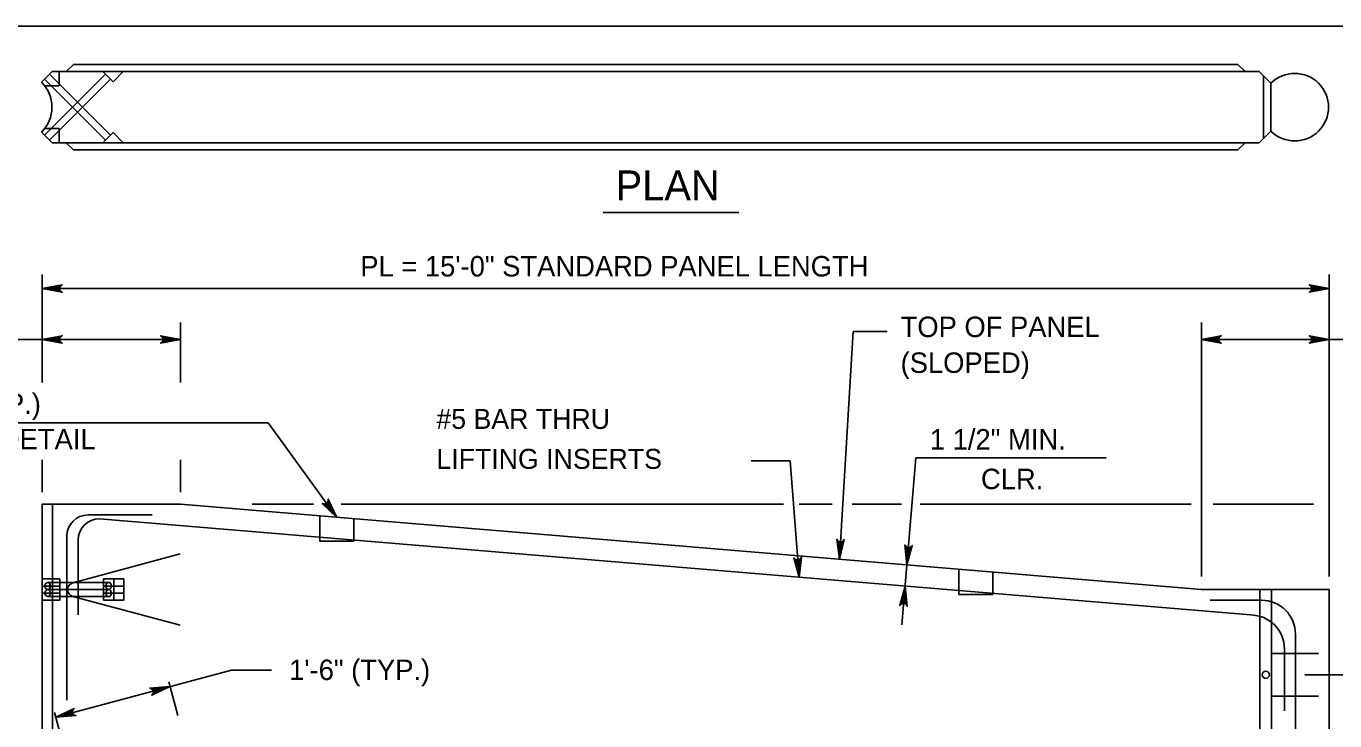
# Model space of a CAD drawing. Extents: x 3385 to 6532, y -616 to 1166.
# Drawn here: x 5133.1 to 5329.7, y 452.4 to 556.7 of the extents above; entities that cross this region are included whole.
import ezdxf

# ---------------------------------------------------------------- set-up
doc = ezdxf.new("R2010")
doc.units = 0
doc.layers.add('1', color=7, linetype='Continuous')
doc.layers.add('2', color=7, linetype='Continuous')

msp = doc.modelspace()

# ---------------------------------------------------------------- linework, layer by layer
at = {"layer": '1'}
for p, q in [((5139.1, 549.87), (5140.17, 550.93)), ((5315.1, 550.93), (5140.17, 550.93)), ((5316.16, 549.87), (5315.1, 550.93)), ((5135.4, 548.3), (5136.97, 549.87)), ((5135.82, 540.35), (5144.98, 549.51)), ((5135.82, 548.72), (5144.98, 539.56)), ((5136.61, 549.51), (5145.77, 540.35)), ((5136.61, 539.56), (5145.77, 548.72)), ((5318.3, 549.87), (5136.97, 549.87)), ((5138.02, 549.87), (5138.02, 547.73)), ((5146.13, 548.36), (5144.62, 549.87)), ((5146.13, 548.36), (5147.63, 549.87)), ((5318.3, 549.87), (5320.05, 548.12)), ((5318.93, 549.23), (5318.93, 539.84)), ((5138.02, 547.73), (5135.88, 547.73)), ((5320.05, 548.11), (5320.05, 540.96)), ((5135.4, 540.77), (5136.97, 539.2)), ((5138.02, 541.33), (5135.88, 541.33)), ((5138.02, 541.33), (5138.02, 539.2)), ((5146.13, 540.71), (5144.62, 539.2)), ((5146.13, 540.71), (5147.63, 539.2)), ((5318.3, 539.2), (5320.05, 540.95)), ((5318.3, 539.2), (5136.97, 539.2)), ((5139.1, 539.2), (5140.17, 538.13)), ((5316.16, 539.2), (5315.1, 538.13)), ((5315.1, 538.13), (5140.17, 538.13)), ((5219.73, 528.7), (5240.11, 528.7)), ((5135.5, 519.39), (5135.5, 503.18)), ((5328.8, 519.39), (5328.8, 474.08)), ((5135.5, 517.29), (5328.8, 517.29)), ((5156.26, 512.21), (5156.26, 503.18)), ((5309.6, 512.21), (5309.6, 474.08)), ((5128.51, 509.66), (5156.26, 509.66)), ((5257.28, 510.87), (5255.23, 476.64)), ((5257.28, 510.87), (5262.42, 510.87)), ((5309.6, 509.66), (5335.1, 509.66)), ((5061.13, 497.15), (5169.45, 497.15)), ((5169.45, 497.15), (5179.75, 482.94)), ((5135.5, 491.58), (5135.5, 486.73)), ((5156.26, 491.58), (5156.26, 486.73)), ((5264.63, 466.82), (5266.72, 491.87)), ((5266.72, 491.87), (5295.32, 491.87)), ((5241.99, 491.42), (5247.85, 491.42)), ((5247.85, 491.42), (5249.19, 473.95)), ((5135.5, 484.9), (5135.5, 329.7)), ((5135.5, 484.9), (5156.26, 484.9)), ((5137.06, 484.9), (5137.06, 329.7)), ((5156.26, 484.9), (5309.6, 472.1)), ((5167.05, 484.9), (5176.22, 484.9)), ((5180.42, 484.9), (5246.84, 484.9)), ((5249.18, 484.9), (5254.13, 484.9)), ((5257.17, 484.9), (5264.57, 484.9)), ((5267.36, 484.9), (5308.06, 484.9)), ((5311.38, 484.9), (5326.45, 484.9)), ((5142.4, 483.3), (5152, 483.3)), ((5144.08, 482.72), (5316.97, 468.29)), ((5177.18, 483.16), (5177.18, 479.36)), ((5182.3, 482.73), (5182.3, 479.36)), ((5139.2, 480.1), (5139.2, 455.47)), ((5140.88, 479.51), (5140.88, 468.32)), ((5177.18, 479.36), (5182.3, 479.36)), ((5156.21, 477.44), (5140.09, 473.12)), ((5273.18, 475.14), (5273.18, 471.35)), ((5278.3, 474.72), (5278.3, 471.35)), ((5145.48, 473.17), (5136.32, 473.17)), ((5145.48, 472.1), (5136.32, 472.1)), ((5146.23, 471.57), (5146.23, 473.7)), ((5309.6, 472.1), (5328.8, 472.1)), ((5318.4, 472.1), (5318.4, 331.3)), ((5320.15, 472.1), (5320.15, 331.3)), ((5328.8, 472.1), (5328.8, 329.7)), ((5145.48, 471.04), (5136.32, 471.04)), ((5140.09, 471.06), (5156.21, 466.74)), ((5146.23, 471.57), (5146.23, 470.5)), ((5273.18, 471.35), (5278.3, 471.35)), ((5310.94, 470.5), (5318.62, 470.5)), ((5323.74, 465.38), (5323.74, 336.42)), ((5320.29, 462.5), (5327.2, 462.5)), ((5322.09, 463.16), (5322.09, 453.89)), ((5137.54, 452.93), (5163.92, 460)), ((5163.92, 460), (5169.91, 460)), ((5155.85, 453.18), (5154.49, 458.23)), ((5325.16, 459.3), (5385.56, 459.3)), ((5320.29, 456.1), (5327.2, 456.1)), ((5138.61, 448.92), (5137.35, 453.64))]:
    msp.add_line(p, q, dxfattribs=at)
for points in [[(5135.5, 517.29), (5138.49, 517.85), (5138.37, 517.77), (5138.26, 517.69), (5138.2, 517.59), (5138.14, 517.49), (5138.12, 517.39), (5138.1, 517.29), (5138.12, 517.19), (5138.14, 517.09), (5138.2, 516.99), (5138.26, 516.89), (5138.37, 516.81), (5138.49, 516.73), (5135.5, 517.29), (5138.37, 516.81), (5138.26, 516.89), (5135.5, 517.29), (5138.2, 516.99), (5138.14, 517.09), (5135.5, 517.29), (5138.12, 517.19), (5138.1, 517.29), (5135.5, 517.29), (5138.12, 517.39), (5138.14, 517.49), (5135.5, 517.29), (5138.2, 517.59), (5138.26, 517.69), (5135.5, 517.29), (5138.37, 517.77)], [(5328.8, 517.29), (5325.82, 516.73), (5325.93, 516.81), (5326.05, 516.89), (5326.11, 516.99), (5326.17, 517.09), (5326.18, 517.19), (5326.2, 517.29), (5326.18, 517.39), (5326.17, 517.49), (5326.11, 517.59), (5326.05, 517.69), (5325.93, 517.77), (5325.82, 517.85), (5328.8, 517.29), (5325.93, 517.77), (5326.05, 517.69), (5328.8, 517.29), (5326.11, 517.59), (5326.17, 517.49), (5328.8, 517.29), (5326.18, 517.39), (5326.2, 517.29), (5328.8, 517.29), (5326.18, 517.19), (5326.17, 517.09), (5328.8, 517.29), (5326.11, 516.99), (5326.05, 516.89), (5328.8, 517.29), (5325.93, 516.81)], [(5135.5, 509.66), (5138.49, 510.22), (5138.26, 510.06), (5138.14, 509.86), (5138.1, 509.66), (5138.14, 509.46), (5138.26, 509.26), (5138.49, 509.1), (5135.5, 509.66), (5138.26, 509.26), (5138.14, 509.46), (5135.5, 509.66), (5138.1, 509.66), (5138.14, 509.86), (5135.5, 509.66), (5138.26, 510.06)], [(5156.26, 509.66), (5153.28, 509.1), (5153.51, 509.26), (5153.63, 509.46), (5153.66, 509.66), (5153.63, 509.86), (5153.51, 510.06), (5153.28, 510.22), (5156.26, 509.66), (5153.51, 510.06), (5153.63, 509.86), (5156.26, 509.66), (5153.66, 509.66), (5153.63, 509.46), (5156.26, 509.66), (5153.51, 509.26)], [(5309.6, 509.66), (5312.58, 510.22), (5312.35, 510.06), (5312.24, 509.86), (5312.2, 509.66), (5312.24, 509.46), (5312.35, 509.26), (5312.58, 509.1), (5309.6, 509.66), (5312.35, 509.26), (5312.24, 509.46), (5309.6, 509.66), (5312.2, 509.66), (5312.24, 509.86), (5309.6, 509.66), (5312.35, 510.06)], [(5328.8, 509.66), (5325.82, 509.1), (5326.05, 509.26), (5326.17, 509.46), (5326.2, 509.66), (5326.17, 509.86), (5326.05, 510.06), (5325.82, 510.22), (5328.8, 509.66), (5326.05, 510.06), (5326.17, 509.86), (5328.8, 509.66), (5326.2, 509.66), (5326.17, 509.46), (5328.8, 509.66), (5326.05, 509.26)], [(5179.75, 482.94), (5177.55, 485.03), (5177.68, 484.98), (5177.81, 484.94), (5177.92, 484.95), (5178.04, 484.96), (5178.13, 485), (5178.22, 485.05), (5178.29, 485.12), (5178.36, 485.19), (5178.41, 485.3), (5178.46, 485.41), (5178.45, 485.55), (5178.45, 485.69), (5179.75, 482.94), (5178.45, 485.55), (5178.46, 485.41), (5179.75, 482.94), (5178.41, 485.3), (5178.36, 485.19), (5179.75, 482.94), (5178.29, 485.12), (5178.22, 485.05), (5179.75, 482.94), (5178.13, 485), (5178.04, 484.96), (5179.75, 482.94), (5177.92, 484.95), (5177.81, 484.94), (5179.75, 482.94), (5177.68, 484.98)], [(5255.23, 476.64), (5254.85, 479.65), (5254.99, 479.41), (5255.19, 479.28), (5255.38, 479.24), (5255.59, 479.26), (5255.79, 479.37), (5255.96, 479.59), (5255.23, 476.64), (5255.79, 479.37), (5255.59, 479.26), (5255.23, 476.64), (5255.38, 479.24), (5255.19, 479.28), (5255.23, 476.64), (5254.99, 479.41)], [(5265.38, 475.79), (5265.07, 478.81), (5265.14, 478.69), (5265.21, 478.57), (5265.3, 478.5), (5265.4, 478.44), (5265.5, 478.41), (5265.59, 478.38), (5265.7, 478.39), (5265.8, 478.4), (5265.9, 478.45), (5266.01, 478.5), (5266.09, 478.61), (5266.18, 478.72), (5265.38, 475.79), (5266.09, 478.61), (5266.01, 478.5), (5265.38, 475.79), (5265.9, 478.45), (5265.8, 478.4), (5265.38, 475.79), (5265.7, 478.39), (5265.59, 478.38), (5265.38, 475.79), (5265.5, 478.41), (5265.4, 478.44), (5265.38, 475.79), (5265.3, 478.5), (5265.21, 478.57), (5265.38, 475.79), (5265.14, 478.69)], [(5249.19, 473.95), (5248.41, 476.88), (5248.49, 476.77), (5248.58, 476.66), (5248.69, 476.61), (5248.79, 476.56), (5248.89, 476.55), (5248.99, 476.54), (5249.09, 476.57), (5249.19, 476.59), (5249.28, 476.66), (5249.38, 476.73), (5249.45, 476.85), (5249.52, 476.97), (5249.19, 473.95), (5249.45, 476.85), (5249.38, 476.73), (5249.19, 473.95), (5249.28, 476.66), (5249.19, 476.59), (5249.19, 473.95), (5249.09, 476.57), (5248.99, 476.54), (5249.19, 473.95), (5248.89, 476.55), (5248.79, 476.56), (5249.19, 473.95), (5248.69, 476.61), (5248.58, 476.66), (5249.19, 473.95), (5248.49, 476.77)], [(5265.11, 472.62), (5265.42, 469.6), (5265.35, 469.72), (5265.28, 469.85), (5265.19, 469.91), (5265.09, 469.98), (5265, 470.01), (5264.9, 470.03), (5264.8, 470.02), (5264.7, 470.01), (5264.59, 469.96), (5264.49, 469.91), (5264.4, 469.8), (5264.31, 469.7), (5265.11, 472.62), (5264.4, 469.8), (5264.49, 469.91), (5265.11, 472.62), (5264.59, 469.96), (5264.7, 470.01), (5265.11, 472.62), (5264.8, 470.02), (5264.9, 470.03), (5265.11, 472.62), (5265, 470.01), (5265.09, 469.98), (5265.11, 472.62), (5265.19, 469.91), (5265.28, 469.85), (5265.11, 472.62), (5265.35, 469.72)], [(5154.68, 457.53), (5151.95, 456.22), (5152.13, 456.43), (5152.19, 456.65), (5152.17, 456.86), (5152.09, 457.04), (5151.92, 457.2), (5151.66, 457.3), (5154.68, 457.53), (5151.92, 457.2), (5152.09, 457.04), (5154.68, 457.53), (5152.17, 456.86), (5152.19, 456.65), (5154.68, 457.53), (5152.13, 456.43)], [(5137.54, 452.93), (5140.27, 454.25), (5140.09, 454.03), (5140.03, 453.81), (5140.05, 453.61), (5140.13, 453.42), (5140.3, 453.26), (5140.56, 453.17), (5137.54, 452.93), (5140.3, 453.26), (5140.13, 453.42), (5137.54, 452.93), (5140.05, 453.61), (5140.03, 453.81), (5137.54, 452.93), (5140.09, 454.03)]]:
    msp.add_lwpolyline(points, dxfattribs=at)
for points in [[(5135.5, 471.57), (5138.13, 471.57), (5138.13, 473.7), (5135.5, 473.7)], [(5135.5, 470.5), (5138.13, 470.5), (5138.13, 472.63), (5135.5, 472.63)], [(5144.72, 471.57), (5147.74, 471.57), (5147.74, 473.7), (5144.72, 473.7)], [(5144.72, 470.5), (5147.74, 470.5), (5147.74, 472.63), (5144.72, 472.63)]]:
    msp.add_lwpolyline(points, close=True, dxfattribs=at)
msp.add_circle((5319.28, 459.3), 0.534, dxfattribs=at)
for centre, radius, start, end in [((5323.63, 544.53), 5.07, 225, 135), ((5131.63, 544.53), 5.32, 314.9993, 45.0018), ((5142.4, 480.1), 3.2, 90, 180), ((5144.08, 479.51), 3.2, 90, 180), ((5140.37, 472.09), 1.07, 105, 255), ((5318.62, 465.38), 5.12, 0, 90), ((5316.97, 463.16), 5.12, 0, 90)]:
    msp.add_arc(centre, radius, start, end, dxfattribs=at)
for centre, major_axis, ratio in [((5136.32, 472.63), (0, 0.534), 0.741868), ((5136.32, 471.57), (0, 0.531), 0.745444), ((5145.48, 472.64), (0, 0.534), 0.741868), ((5145.48, 471.56), (0, 0.534), 0.741868)]:
    msp.add_ellipse(centre, major_axis=major_axis, ratio=ratio, dxfattribs=at)
at = {"layer": '2'}
msp.add_line((4642.34, 556.69), (5428.34, 556.69), dxfattribs=at)

# ---------------------------------------------------------------- texts
at = {"layer": '1'}
for s, height, p in [('PLAN', 4.477, (5221.62, 530.55)), ('PL = 15\'-0" STANDARD PANEL LENGTH', 3.072, (5183.27, 519.11)), ('TOP OF PANEL', 3.072, (5264.43, 510.01)), ('(SLOPED)', 3.072, (5264.43, 504.63)), ('GALVANIZED LIFTING INSERT (TYP.)', 3.072, (5063.17, 498.46)), ('#5 BAR THRU', 3, (5194.7, 496.22)), ('(SEE LIFTING INSERT LOCATION DETAIL ', 3.072, (5063.17, 493.15)), ('1 1/2" MIN.', 3.072, (5268.82, 493.12)), ('LIFTING INSERTS', 3, (5194.7, 490.22)), ('CLR.', 3.072, (5276.5, 487.17)), ('1\'-6" (TYP.)', 3.072, (5172.58, 458.51))]:
    msp.add_text(s, height=height, dxfattribs=at).set_placement(p)

doc.saveas('drawing.dxf')
